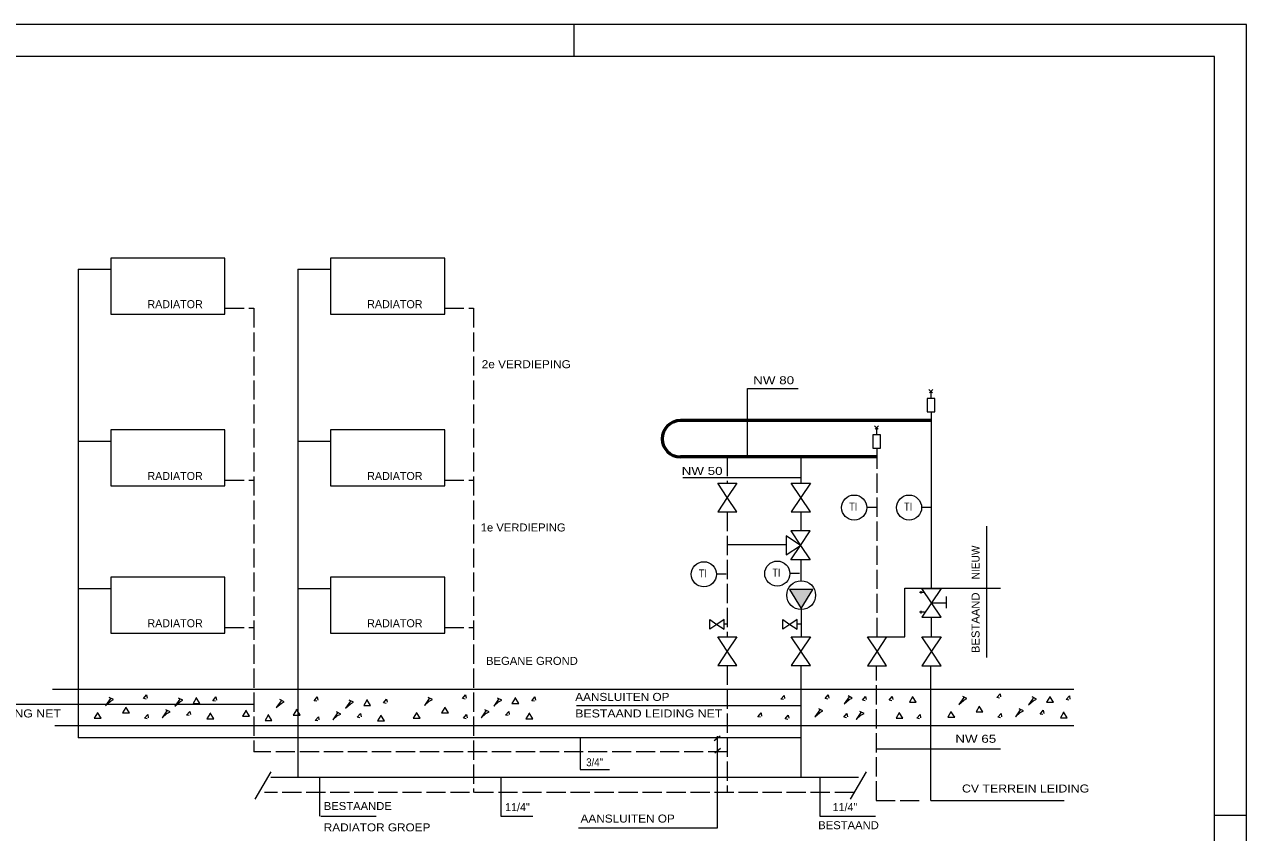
# Model space of a CAD drawing. Extents: x 295824 to 414724, y 24924 to 109024.
# Drawn here: x 376562 to 414724, y 83782 to 109024 of the extents above; entities that cross this region are included whole.
import ezdxf

# ---------------------------------------------------------------- set-up
doc = ezdxf.new("R2010")
doc.units = 0
doc.header["$LTSCALE"] = 100
doc.linetypes.add('LONG_DASHED', pattern=[7.5, 6, -1.5])
for name, color, linetype, lineweight in [('1', 7, 'Continuous', 13), ('14', 7, 'Continuous', 13), ('16', 7, 'Continuous', 13)]:
    doc.layers.add(name, color=color, linetype=linetype, lineweight=lineweight)

msp = doc.modelspace()

# ---------------------------------------------------------------- hatches: boundary and pattern name
at = {"layer": '16'}
msp.add_hatch(color=256, dxfattribs=at).paths.add_polyline_path([(401176.6, 91376.8), (400456.6, 91376.8), (400816.6, 90776.8), (400816.6, 90776.8)])

# ---------------------------------------------------------------- linework, layer by layer
at = {"layer": '1'}
for p, q in [((393723.6, 108023.8), (393723.6, 109023.8)), ((414723.6, 24923.8), (414723.6, 109023.8)), ((377443.2, 88259.9), (409329.9, 88259.9)), ((377509.8, 87126.6), (409329.9, 87126.6)), ((413723.6, 84323.8), (414723.6, 84323.8))]:
    msp.add_line(p, q, dxfattribs=at)
for points in [[(414723.6, 109023.8), (304995.6, 109023.8), (295823.6, 109023.8)], [(304995.6, 25923.8), (413723.6, 25923.8), (413723.6, 108023.8), (304995.6, 108023.8)]]:
    msp.add_lwpolyline(points, dxfattribs=at)
at = {"layer": '14'}
for points in [[(398209.7, 94697.2), (398809.7, 94697.2), (398509.7, 94247.2)], [(400508.3, 94697.2), (401108.3, 94697.2), (400808.3, 94247.2)], [(398209.7, 93797.2), (398809.7, 93797.2), (398509.7, 94247.2)], [(400508.3, 93797.2), (401108.3, 93797.2), (400808.3, 94247.2)], [(404582.8, 91409.8), (405182.8, 91409.8), (404882.8, 90959.8)], [(404582.8, 90509.8), (405182.8, 90509.8), (404882.8, 90959.8)], [(398209.7, 89897.3), (398809.7, 89897.3), (398509.7, 89447.3)], [(400508.3, 89897.3), (401108.3, 89897.3), (400808.3, 89447.3)], [(402883.9, 89893.2), (403483.9, 89893.2), (403183.9, 89443.2)], [(404582.8, 89893.2), (405182.8, 89893.2), (404882.8, 89443.2)], [(398209.7, 88997.3), (398809.7, 88997.3), (398509.7, 89447.3)], [(400508.3, 88997.3), (401108.3, 88997.3), (400808.3, 89447.3)], [(402883.9, 88993.2), (403483.9, 88993.2), (403183.9, 89443.2)], [(404582.8, 88993.2), (405182.8, 88993.2), (404882.8, 89443.2)]]:
    msp.add_lwpolyline(points, close=True, dxfattribs=at)
at = {"layer": '16'}
for p, q in [((378241.4, 101374.5), (378241.4, 86736.4)), ((378241.4, 101374.5), (379258.4, 101374.5)), ((385103.8, 101374.5), (385103.8, 85503.1)), ((385103.8, 101374.5), (386120.8, 101374.5)), ((404806.4, 97624.4), (404918.8, 97511.9)), ((404823, 97516), (404931.3, 97624.3)), ((404873, 97341), (404873, 97566)), ((404882.8, 96649.7), (404882.8, 96916.1)), ((404882.8, 91428.7), (404882.8, 96649.7)), ((403107.4, 96491.1), (403219.9, 96378.6)), ((403124.1, 96382.7), (403232.4, 96491)), ((403174, 96207.7), (403174, 96432.7)), ((378241.4, 96007.9), (379258.4, 96007.9)), ((385103.8, 96007.9), (386120.8, 96007.9)), ((400808.6, 95516.4), (400808.6, 94697.2)), ((403183.9, 95516.4), (403183.9, 95782.8)), ((400829.9, 94861.2), (397115.6, 94861.2)), ((403161.8, 93936.2), (402877.4, 93936.2)), ((404877.4, 93936.2), (404593, 93936.2)), ((400808.6, 93797.2), (400808.6, 93217.8)), ((406605, 93349.8), (406605, 89249.9)), ((400343.4, 92767.8), (398510.1, 92767.8)), ((400808.6, 92299.5), (400808.6, 91646.7)), ((398469.3, 91852.3), (398184.9, 91852.3)), ((400761.8, 91873.9), (400477.5, 91873.9)), ((378241.4, 91408), (379258.4, 91408)), ((385103.8, 91408), (386120.8, 91408)), ((400456.6, 91376.8), (400816.6, 90776.8)), ((401176.6, 91376.8), (400456.6, 91376.8)), ((400816.6, 90776.8), (401176.6, 91376.8)), ((404056.8, 91419.5), (407038.1, 91419.5)), ((404664.8, 91278.7), (404514.9, 91278.7)), ((404549.2, 91319.8), (404549.2, 91244.8)), ((404881.3, 90962), (405322.7, 90962)), ((405339.4, 91153.7), (405339.4, 90795.4)), ((400816.6, 90746.8), (400816.6, 89897.2)), ((404664.8, 90662), (404514.9, 90662)), ((404549.2, 90703.2), (404549.2, 90628.2)), ((404882.8, 89893.2), (404882.8, 90509.8)), ((398526.7, 90286.7), (398410.6, 90286.7)), ((400808.6, 90286.7), (400692.5, 90286.7)), ((400808.6, 88997.3), (400808.6, 85503.1)), ((404866, 84785), (404866, 88993.2)), ((383727.1, 87777.8), (373178.7, 87777.8)), ((400808.6, 87739.7), (393796.2, 87739.7)), ((400808.6, 86736.4), (378241.4, 86736.4)), ((398282, 86792.2), (398098.8, 86642.2)), ((398196.4, 86790.6), (398196.4, 83924)), ((398298.7, 86408.9), (398115.5, 86258.9)), ((403173.8, 86399.9), (407038.1, 86399.9)), ((384252.6, 85680.1), (383758.5, 84824.3)), ((402607.8, 85503.1), (384252.5, 85503.1)), ((385779.5, 85496.9), (385779.5, 84297)), ((402841, 85680.1), (402346.9, 84824.3)), ((404866, 84785), (409030.1, 84785)), ((385812.9, 84297), (387545.1, 84297)), ((398196.4, 83924), (393865.8, 83924))]:
    msp.add_line(p, q, dxfattribs=at)
at = {"layer": '16', "linetype": 'LONG_DASHED'}
for p, q in [((382823.3, 100156.6), (383720, 100156.6)), ((383720, 100156.6), (383720, 86303.1)), ((389685.7, 100156.6), (390582.4, 100156.6)), ((390582.4, 100156.6), (390582.4, 85036.4)), ((398510.1, 95516.4), (398510.1, 94697.2)), ((403183.9, 89893.2), (403183.9, 95516.4)), ((382823.3, 94790.1), (383720, 94790.1)), ((389685.7, 94790.1), (390582.4, 94790.1)), ((398510.1, 93797.2), (398510.1, 89897.3)), ((382823.3, 90190.1), (383720, 90190.1)), ((389685.7, 90190.1), (390582.4, 90190.1)), ((398510.1, 88997.3), (398510.1, 85036.4)), ((403167.1, 84785), (403167.1, 88993.2)), ((398510.1, 86303.1), (383720, 86303.1)), ((402462.2, 85036.4), (384052.7, 85036.4)), ((403152.7, 84785), (404615, 84785))]:
    msp.add_line(p, q, dxfattribs=at)
at = {"layer": '16', "lineweight": 53}
for p, q in [((404882.8, 96649.7), (397044.3, 96649.7)), ((403183.9, 95516.4), (397044.3, 95516.4))]:
    msp.add_line(p, q, dxfattribs=at)
at = {"layer": '16'}
for points in [[(379258.4, 99973.8), (382823.3, 99973.8), (382823.3, 101724.7), (379258.4, 101724.7)], [(386120.8, 99973.8), (389685.7, 99973.8), (389685.7, 101724.7), (386120.8, 101724.7)], [(404748, 96920.2), (404989.8, 96920.2), (404989.8, 97339), (404748, 97339)], [(379258.4, 94607.2), (382823.3, 94607.2), (382823.3, 96358.1), (379258.4, 96358.1)], [(386120.8, 94607.2), (389685.7, 94607.2), (389685.7, 96358.1), (386120.8, 96358.1)], [(403049.1, 95786.9), (403290.9, 95786.9), (403290.9, 96205.7), (403049.1, 96205.7)], [(401093.4, 93202.9), (400493.4, 93202.9), (400793.4, 92752.9)], [(400343.4, 93052.9), (400343.4, 92452.9), (400793.4, 92752.9)], [(401093.4, 92302.9), (400493.4, 92302.9), (400793.4, 92752.9)], [(379258.4, 90007.3), (382823.3, 90007.3), (382823.3, 91758.2), (379258.4, 91758.2)], [(386120.8, 90007.3), (389685.7, 90007.3), (389685.7, 91758.2), (386120.8, 91758.2)], [(401176.6, 91376.8), (400456.6, 91376.8), (400816.6, 90776.8), (400816.6, 90776.8)], [(397959.3, 90135.2), (397959.3, 90435.2), (398184.3, 90285.2)], [(398409.3, 90135.2), (398409.3, 90435.2), (398184.3, 90285.2)], [(400241.2, 90135.2), (400241.2, 90435.2), (400466.2, 90285.2)], [(400691.2, 90135.2), (400691.2, 90435.2), (400466.2, 90285.2)]]:
    msp.add_lwpolyline(points, close=True, dxfattribs=at)
for points in [[(399143, 95516.4), (399143, 97649.7), (400725.2, 97649.7)], [(403483.9, 89893.2), (404056.8, 89893.2), (404056.8, 91419.5)], [(379243.9, 87967.2), (379094, 87750.5), (379243.9, 87883.8), (379343.8, 87933.8), (379210.5, 88000.5)], [(380359.8, 87950.5), (380276.5, 87967.2), (380376.5, 88083.8), (380393.2, 87983.8)], [(381409.2, 87950.5), (381259.3, 87733.8), (381409.2, 87867.2), (381509.1, 87917.2), (381375.9, 87983.8)], [(381925.5, 87983.8), (381825.6, 87817.2), (382042.1, 87817.2), (381925.5, 88000.5)], [(382525.2, 87883.8), (382441.9, 87900.5), (382541.8, 88017.2), (382558.5, 87917.2)], [(384573.9, 87900.5), (384424, 87683.8), (384573.9, 87817.2), (384673.8, 87867.2), (384540.6, 87933.8)], [(385689.9, 87883.8), (385606.6, 87900.5), (385706.5, 88017.2), (385723.2, 87917.2)], [(386739.2, 87883.8), (386589.3, 87667.2), (386739.2, 87800.5), (386839.1, 87850.5), (386705.9, 87917.2)], [(387255.5, 87917.2), (387155.6, 87750.5), (387372.1, 87750.5), (387255.5, 87933.8)], [(387855.2, 87817.2), (387771.9, 87833.8), (387871.8, 87950.5), (387888.5, 87850.5)], [(389204.3, 87967.2), (389054.4, 87750.5), (389204.3, 87883.8), (389304.3, 87933.8), (389171, 88000.5)], [(390320.3, 87950.5), (390237, 87967.2), (390337, 88083.8), (390353.6, 87983.8)], [(391369.7, 87950.5), (391219.7, 87733.8), (391369.7, 87867.2), (391469.6, 87917.2), (391336.3, 87983.8)], [(391886, 87983.8), (391786.1, 87817.2), (392002.6, 87817.2), (391886, 88000.5)], [(392485.6, 87883.8), (392402.3, 87900.5), (392502.3, 88017.2), (392518.9, 87917.2)], [(400264.1, 87933.8), (400180.8, 87950.5), (400280.8, 88067.2), (400297.4, 87967.2)], [(401646.6, 87950.5), (401563.3, 87967.2), (401663.2, 88083.8), (401679.9, 87983.8)], [(402312.8, 88017.2), (402162.9, 87800.5), (402312.8, 87933.8), (402412.8, 87983.8), (402279.5, 88050.5)], [(402812.5, 87900.5), (402729.2, 87917.2), (402829.2, 88033.8), (402845.8, 87933.8)], [(403645.3, 87900.5), (403562, 87917.2), (403662, 88033.8), (403678.7, 87933.8)], [(404294.9, 88017.2), (404195, 87850.5), (404411.5, 87850.5), (404294.9, 88033.8)], [(405893.9, 88000.5), (405744, 87783.8), (405893.9, 87917.2), (405993.9, 87967.2), (405860.6, 88033.8)], [(407009.9, 87983.8), (406926.6, 88000.5), (407026.6, 88117.2), (407043.2, 88017.2)], [(408059.3, 87983.8), (407909.4, 87767.2), (408059.3, 87900.5), (408159.2, 87950.5), (408026, 88017.2)], [(408575.6, 88017.2), (408475.7, 87850.5), (408692.2, 87850.5), (408575.6, 88033.8)], [(409175.2, 87917.2), (409092, 87933.8), (409191.9, 88050.5), (409208.5, 87950.5)], [(378844.1, 87517.2), (378744.2, 87350.5), (378960.7, 87350.5), (378844.1, 87533.9)], [(379726.9, 87683.8), (379627, 87517.2), (379843.5, 87517.2), (379726.9, 87700.5)], [(380393.2, 87333.9), (380309.9, 87350.5), (380409.8, 87467.2), (380426.5, 87367.2)], [(381009.4, 87583.8), (380859.5, 87367.2), (381009.4, 87500.5), (381109.4, 87550.5), (380976.1, 87617.2)], [(381709, 87433.9), (381625.7, 87450.5), (381725.7, 87567.2), (381742.3, 87467.2)], [(382358.6, 87500.5), (382258.7, 87333.9), (382475.2, 87333.9), (382358.6, 87517.2)], [(383474.6, 87583.8), (383374.6, 87417.2), (383591.2, 87417.2), (383474.6, 87600.5)], [(384174.1, 87450.5), (384074.2, 87283.9), (384290.7, 87283.9), (384174.1, 87467.2)], [(385056.9, 87617.2), (384957, 87450.5), (385173.5, 87450.5), (385056.9, 87633.8)], [(385723.2, 87267.2), (385639.9, 87283.9), (385739.8, 87400.5), (385756.5, 87300.5)], [(386339.5, 87517.2), (386189.5, 87300.5), (386339.5, 87433.8), (386439.4, 87483.8), (386306.1, 87550.5)], [(387039, 87367.2), (386955.7, 87383.9), (387055.7, 87500.5), (387072.3, 87400.5)], [(387688.6, 87433.8), (387588.7, 87267.2), (387805.2, 87267.2), (387688.6, 87450.5)], [(388804.6, 87517.2), (388704.7, 87350.5), (388921.2, 87350.5), (388804.6, 87533.8)], [(389687.4, 87683.8), (389587.4, 87517.2), (389804, 87517.2), (389687.4, 87700.5)], [(390353.6, 87333.8), (390270.3, 87350.5), (390370.3, 87467.2), (390386.9, 87367.2)], [(390969.9, 87583.8), (390820, 87367.2), (390969.9, 87500.5), (391069.8, 87550.5), (390936.6, 87617.2)], [(391669.5, 87433.8), (391586.2, 87450.5), (391686.1, 87567.2), (391702.8, 87467.2)], [(392319.1, 87500.5), (392219.1, 87333.8), (392435.7, 87333.8), (392319.1, 87517.2)], [(399547.9, 87383.8), (399464.6, 87400.5), (399564.5, 87517.2), (399581.2, 87417.2)], [(400397.4, 87317.2), (400314.1, 87333.8), (400414, 87450.5), (400430.7, 87350.5)], [(401396.7, 87617.2), (401246.8, 87400.5), (401396.7, 87533.8), (401496.7, 87583.8), (401363.4, 87650.5)], [(402229.6, 87367.2), (402146.3, 87383.8), (402246.2, 87500.5), (402262.9, 87400.5)], [(402679.3, 87533.8), (402529.4, 87317.2), (402679.3, 87450.5), (402779.2, 87500.5), (402646, 87567.2)], [(403878.5, 87517.2), (403778.6, 87350.5), (403995.1, 87350.5), (403878.5, 87533.8)], [(404511.5, 87333.8), (404428.2, 87350.5), (404528.1, 87467.2), (404544.8, 87367.2)], [(405494.2, 87550.5), (405394.3, 87383.8), (405610.8, 87383.8), (405494.2, 87567.2)], [(406377, 87717.2), (406277, 87550.5), (406493.6, 87550.5), (406377, 87733.8)], [(407043.2, 87367.2), (406959.9, 87383.8), (407059.9, 87500.5), (407076.5, 87400.5)], [(407659.5, 87617.2), (407509.6, 87400.5), (407659.5, 87533.8), (407759.5, 87583.8), (407626.2, 87650.5)], [(408359.1, 87467.2), (408275.8, 87483.8), (408375.7, 87600.5), (408392.4, 87500.5)], [(409008.7, 87533.8), (408908.7, 87367.2), (409125.3, 87367.2), (409008.7, 87550.5)], [(393913.2, 86746.8), (393913.2, 85746.8), (394829.3, 85746.8)], [(391442.7, 85496.9), (391442.7, 84297), (392433.8, 84297)], [(401403.2, 85496.9), (401403.2, 84297), (403135.4, 84297)]]:
    msp.add_lwpolyline(points, dxfattribs=at)
for centre, radius in [((402470.2, 93933.6), 392.1), ((404185.8, 93933.6), 392.1), ((397777.6, 91849.7), 392.1), ((400070.2, 91871.3), 392.1), ((400816.6, 91196.8), 450)]:
    msp.add_circle(centre, radius, dxfattribs=at)
at = {"layer": '16', "lineweight": 53}
msp.add_arc((397044.3, 96083.1), 566.6, 90, 270, dxfattribs=at)

# ---------------------------------------------------------------- texts
at = {"layer": '16'}
for s, p in [('RADIATOR', (380402.1, 100161.5)), ('RADIATOR', (387264.5, 100161.5)), ('RADIATOR', (380402.1, 94794.9)), ('RADIATOR', (387264.5, 94794.9)), ('RADIATOR', (380402.1, 90195)), ('RADIATOR', (387264.5, 90195)), ('11/4"', (391571.6, 84452.9)), ('11/4"', (401798.6, 84452.9))]:
    msp.add_text(s, height=250, dxfattribs=at).set_placement(p)
for s, width, p in [('2e VERDIEPING', 1.1, (390841.7, 98286.7)), ('NW 80', 1.25, (399318.1, 97784.7)), ('NW 50', 1.25, (397084.9, 94952.7)), ('TI', 0.85, (402315.3, 93839.2)), ('TI', 0.85, (404030.9, 93839.2)), ('1e VERDIEPING', 1.05, (390808.4, 93186.8)), ('TI', 0.85, (397622.7, 91755.3)), ('TI', 0.85, (399915.3, 91776.9)), ('BEGANE GROND', 1.05, (390975, 89020.2)), ('AANSLUITEN OP', 1.1, (393761, 87894.3)), ('BESTAAND LEIDING NET', 1.15, (373107.2, 87377.7)), ('BESTAAND LEIDING NET', 1.15, (393761, 87377.7)), ('NW 65', 1.25, (405629.5, 86586.2)), ('3/4"', 0.9, (394103.4, 85852.9)), ('CV TERREIN LEIDING', 1.15, (405837.2, 85033.1)), ('BESTAANDE', 1.05, (385908.5, 84486.3)), ('AANSLUITEN OP', 1.1, (393927.5, 84094.4)), ('RADIATOR GROEP', 1.1, (385908.5, 83819.6)), ('BESTAAND', 1.05, (401348.9, 83886.3))]:
    msp.add_text(s, height=250, dxfattribs=dict(at, width=width)).set_placement(p)
for s, width, p in [('NIEUW', 0.95, (406385.9, 91689.2)), ('BESTAAND', 1.05, (406385.9, 89389.3))]:
    msp.add_text(s, height=250, rotation=90, dxfattribs=dict(at, width=width)).set_placement(p)

doc.saveas('drawing.dxf')
